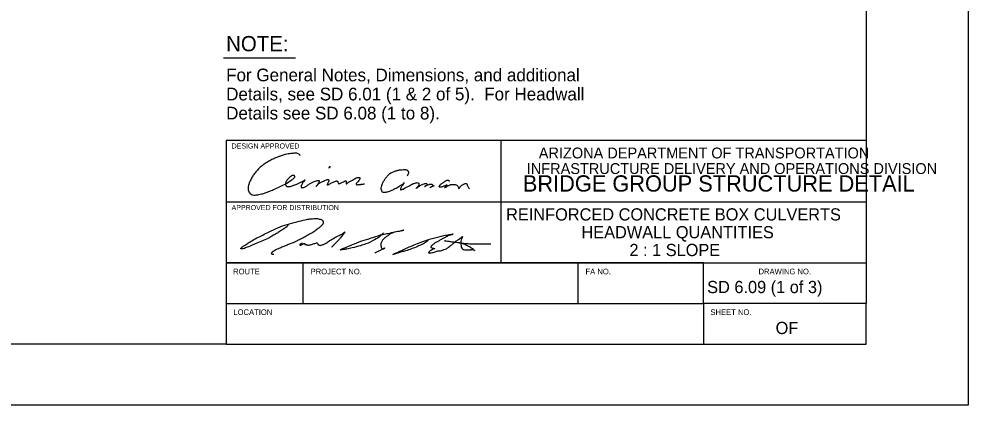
# Model space of a CAD drawing. Extents: x -0.08 to 2.83, y -0.03 to 1.92.
# Drawn here: x 1.862 to 2.833, y 0 to 0.395 of the extents above; entities that cross this region are included whole.
import ezdxf

# ---------------------------------------------------------------- set-up
doc = ezdxf.new("R2010")
doc.units = 0
for name, color, linetype in [('55', 7, 'Continuous'), ('57', 7, 'Continuous'), ('62', 7, 'Continuous'), ('63', 7, 'Continuous')]:
    doc.layers.add(name, color=color, linetype=linetype)

msp = doc.modelspace()

# ---------------------------------------------------------------- linework, layer by layer
at = {"layer": '55'}
for points in [[(2.15001, 0.25543), (2.14758, 0.25741), (2.14617, 0.25785), (2.14423, 0.25794), (2.14225, 0.25776), (2.1402, 0.25761), (2.13722, 0.2572), (2.13461, 0.25674), (2.13312, 0.25633), (2.13139, 0.2557), (2.1309, 0.25548), (2.1279, 0.25446), (2.12484, 0.2532), (2.1206, 0.25132), (2.11648, 0.24906), (2.11297, 0.24683), (2.10987, 0.24445), (2.10588, 0.24062), (2.10299, 0.237), (2.10059, 0.23378), (2.09857, 0.22978), (2.09735, 0.22698), (2.09658, 0.22347), (2.09632, 0.22083), (2.0965, 0.22021), (2.09681, 0.21951), (2.09723, 0.21833), (2.098, 0.21721), (2.09936, 0.21582), (2.101, 0.2152), (2.10355, 0.21505), (2.10736, 0.21566), (2.10994, 0.21625), (2.11399, 0.21726), (2.11746, 0.21865), (2.1224, 0.22067), (2.12858, 0.22356), (2.13414, 0.22632), (2.14122, 0.23075), (2.14355, 0.23265), (2.1438, 0.23291), (2.14403, 0.23351), (2.14403, 0.23426), (2.14395, 0.23467), (2.14366, 0.23506), (2.14306, 0.23523), (2.14231, 0.23519), (2.14138, 0.23496), (2.14015, 0.23417), (2.13831, 0.23262), (2.1366, 0.23096), (2.1355, 0.22937), (2.13485, 0.2278), (2.13469, 0.22641), (2.13471, 0.22546), (2.13499, 0.22483), (2.13551, 0.2243), (2.13614, 0.22393), (2.13712, 0.22378), (2.13865, 0.22378), (2.14061, 0.22424), (2.1439, 0.22538), (2.14709, 0.22656), (2.14964, 0.22791), (2.15235, 0.22918), (2.1548, 0.23064), (2.15321, 0.22863), (2.15278, 0.22814), (2.15212, 0.22718), (2.15124, 0.22569), (2.15055, 0.22402), (2.15062, 0.22327), (2.15113, 0.2227), (2.15171, 0.22264), (2.15353, 0.2229), (2.15492, 0.22351), (2.15731, 0.22511), (2.15997, 0.22683), (2.16276, 0.22826), (2.16513, 0.22931), (2.1672, 0.22997), (2.16877, 0.23003), (2.16885, 0.23001), (2.16905, 0.22994), (2.16916, 0.22971), (2.16921, 0.22923), (2.16902, 0.22873), (2.16846, 0.22743), (2.1677, 0.22608), (2.16569, 0.22382), (2.16628, 0.22431), (2.16828, 0.22641), (2.16883, 0.2268), (2.16988, 0.2275), (2.1711, 0.22812), (2.17281, 0.229), (2.17455, 0.2298), (2.17652, 0.23053), (2.17805, 0.23107), (2.17845, 0.23099), (2.17884, 0.23056), (2.17886, 0.22947), (2.17831, 0.22798), (2.17796, 0.22723), (2.17731, 0.22578), (2.17716, 0.22546), (2.17716, 0.22538), (2.17753, 0.22539), (2.17821, 0.22565), (2.17895, 0.22596), (2.18003, 0.22647), (2.18113, 0.22707), (2.18425, 0.22854), (2.18595, 0.22925), (2.18701, 0.22947), (2.18751, 0.22945), (2.18764, 0.22938), (2.18777, 0.22927), (2.18805, 0.22878), (2.18849, 0.22777), (2.18919, 0.22648), (2.1903, 0.2268), (2.19162, 0.22742), (2.19305, 0.22818), (2.19472, 0.22898), (2.1958, 0.22955), (2.19618, 0.2297), (2.19652, 0.22948), (2.19677, 0.22899), (2.19681, 0.22851), (2.19688, 0.22708), (2.19689, 0.22654), (2.19699, 0.2265), (2.19794, 0.22713), (2.20054, 0.22882), (2.20306, 0.23041), (2.20516, 0.23164), (2.20697, 0.23255), (2.20839, 0.23299), (2.21006, 0.23312), (2.2106, 0.23289), (2.21082, 0.23247), (2.2109, 0.23199), (2.21081, 0.23152), (2.2104, 0.23086), (2.20965, 0.2299), (2.20831, 0.22816), (2.20712, 0.22678), (2.20699, 0.22618), (2.20715, 0.22586), (2.2085, 0.22567), (2.20942, 0.22576), (2.21055, 0.22588), (2.21161, 0.22603), (2.21247, 0.22616), (2.21418, 0.22636), (2.21539, 0.22668)], [(2.17986, 0.24471), (2.17999, 0.24419), (2.17945, 0.24328), (2.17891, 0.24254), (2.18016, 0.24389), (2.18061, 0.24401)], [(2.25913, 0.23472), (2.26029, 0.23637), (2.26076, 0.23774), (2.26076, 0.23856), (2.26062, 0.23911), (2.26004, 0.23992), (2.25945, 0.24026), (2.2583, 0.24058), (2.25644, 0.2408), (2.25422, 0.2407), (2.25114, 0.2404), (2.24777, 0.23963), (2.2448, 0.23864), (2.24155, 0.23685), (2.23882, 0.23456), (2.2377, 0.23304), (2.2365, 0.23153), (2.23482, 0.22905), (2.23317, 0.22562), (2.23251, 0.22313), (2.2323, 0.22157), (2.2325, 0.22061), (2.23275, 0.2199), (2.23334, 0.21882), (2.23414, 0.21819), (2.23498, 0.21801), (2.2361, 0.21789), (2.23696, 0.21795), (2.23781, 0.21809), (2.23899, 0.21844), (2.24106, 0.21913), (2.24338, 0.21998), (2.24568, 0.22106), (2.24791, 0.22222), (2.25148, 0.22431), (2.25408, 0.22593), (2.25528, 0.22699), (2.25596, 0.22758), (2.2558, 0.22724), (2.25569, 0.22701), (2.25442, 0.2253), (2.25333, 0.22375), (2.25269, 0.22234), (2.25245, 0.22167), (2.25221, 0.22097), (2.25221, 0.22077), (2.25227, 0.22059), (2.25263, 0.22047), (2.25298, 0.22053), (2.2536, 0.22067), (2.25502, 0.22125), (2.26074, 0.22419), (2.26545, 0.22673), (2.26732, 0.22736), (2.26877, 0.22774), (2.26999, 0.22768), (2.27076, 0.22738), (2.27111, 0.22675), (2.27112, 0.22556), (2.27102, 0.22481), (2.27061, 0.22411), (2.26819, 0.22181), (2.27093, 0.22373), (2.27398, 0.22556), (2.27644, 0.22654), (2.27843, 0.22689), (2.27927, 0.22661), (2.27985, 0.2258), (2.27977, 0.22554), (2.27976, 0.22537), (2.27941, 0.22518), (2.2786, 0.22453), (2.27706, 0.22375), (2.27972, 0.22513), (2.28179, 0.22589), (2.28256, 0.22619), (2.28403, 0.22629), (2.28469, 0.22599), (2.28517, 0.22525), (2.28515, 0.22471), (2.28492, 0.22428), (2.28393, 0.22344), (2.28235, 0.22249), (2.28532, 0.22412), (2.28733, 0.22492)], [(2.30267, 0.22892), (2.30234, 0.22949), (2.3018, 0.22993), (2.30131, 0.23009), (2.3008, 0.23009), (2.30032, 0.23003), (2.29957, 0.22989), (2.29894, 0.22961), (2.29775, 0.22894), (2.29677, 0.22833), (2.29582, 0.22761), (2.29429, 0.22651), (2.29321, 0.22567), (2.29216, 0.2246), (2.29189, 0.22405), (2.2918, 0.22362), (2.29182, 0.22366), (2.29199, 0.22348), (2.29251, 0.22335), (2.2936, 0.22339), (2.29501, 0.22377), (2.29629, 0.22413), (2.29798, 0.2247), (2.29932, 0.22536), (2.29957, 0.22541), (2.29976, 0.2253), (2.29981, 0.2252), (2.29975, 0.225), (2.29959, 0.2248), (2.29831, 0.22373), (2.29744, 0.22287), (2.29735, 0.22276), (2.29743, 0.2227), (2.29781, 0.22277), (2.2988, 0.22329), (2.30057, 0.22435), (2.30188, 0.225), (2.30392, 0.22573), (2.3061, 0.22604), (2.30849, 0.22581), (2.30949, 0.22544), (2.31036, 0.22475), (2.31091, 0.22411), (2.3116, 0.22265), (2.31196, 0.22161), (2.3126, 0.22233), (2.31334, 0.22346), (2.31434, 0.22457), (2.31582, 0.22566), (2.31756, 0.2264), (2.31949, 0.22699), (2.31976, 0.22691), (2.32023, 0.22668), (2.3207, 0.22516), (2.32126, 0.22398), (2.32189, 0.22286), (2.32233, 0.22209), (2.32292, 0.22145)], [(2.13692, 0.18516), (2.13711, 0.18449), (2.13708, 0.18402), (2.13681, 0.18349), (2.13589, 0.18255), (2.13195, 0.17982), (2.12821, 0.17738), (2.12437, 0.17504), (2.11671, 0.17069), (2.10374, 0.16502), (2.10229, 0.16443), (2.09999, 0.1634), (2.09376, 0.16092), (2.09139, 0.16014), (2.09018, 0.15994), (2.08919, 0.15985), (2.08904, 0.15989), (2.08875, 0.16017), (2.08886, 0.16035), (2.08914, 0.16074), (2.09001, 0.16165), (2.09361, 0.16401), (2.0971, 0.16634), (2.1021, 0.16941), (2.10864, 0.17274), (2.11998, 0.17836), (2.1292, 0.18259), (2.13862, 0.18561), (2.14876, 0.18833), (2.15642, 0.19001), (2.16054, 0.19071), (2.1641, 0.1909), (2.16637, 0.19094), (2.1683, 0.19075), (2.17023, 0.19028), (2.1718, 0.18974), (2.17245, 0.18918), (2.17281, 0.18877), (2.17307, 0.18808), (2.17324, 0.18741), (2.17323, 0.18698), (2.17317, 0.1864), (2.17305, 0.18598), (2.17272, 0.18537), (2.17195, 0.18431), (2.17071, 0.18308), (2.16807, 0.18073), (2.16459, 0.17812), (2.16054, 0.17558), (2.15565, 0.17281), (2.15245, 0.171), (2.14775, 0.16877), (2.14512, 0.16756), (2.13957, 0.16509), (2.1355, 0.16347), (2.13193, 0.16192), (2.12769, 0.16032), (2.12482, 0.15889), (2.12278, 0.15776), (2.12183, 0.1571), (2.12131, 0.15676), (2.12086, 0.15632), (2.12046, 0.15586), (2.12012, 0.15542), (2.12011, 0.15537), (2.12011, 0.15526), (2.1202, 0.15509), (2.12036, 0.15488), (2.12062, 0.15472), (2.12115, 0.15459), (2.12156, 0.15459), (2.12236, 0.15462), (2.12266, 0.15463)], [(2.15215, 0.16533), (2.15165, 0.16558), (2.15087, 0.16542), (2.1497, 0.16466), (2.14918, 0.16411), (2.14918, 0.16383), (2.1495, 0.16362), (2.15043, 0.16388), (2.15113, 0.16407), (2.15248, 0.16463), (2.15357, 0.16535), (2.15403, 0.16543), (2.15418, 0.16544), (2.15443, 0.16515), (2.1544, 0.16455), (2.15476, 0.16431), (2.15544, 0.16432), (2.15619, 0.16415), (2.15697, 0.16398), (2.15772, 0.16378), (2.15893, 0.16383), (2.1601, 0.16421), (2.16212, 0.16481), (2.16403, 0.16537), (2.16566, 0.16582), (2.16712, 0.16606), (2.16767, 0.16496), (2.16804, 0.16429), (2.1689, 0.16384), (2.17004, 0.16347), (2.17128, 0.16384), (2.17298, 0.16426), (2.1762, 0.16591), (2.18, 0.16838), (2.18508, 0.17145), (2.19087, 0.17445), (2.1937, 0.17599), (2.19558, 0.1773), (2.19408, 0.17539), (2.19361, 0.17483), (2.193, 0.17404), (2.19158, 0.17212), (2.19036, 0.17057), (2.18805, 0.16806), (2.18628, 0.16609), (2.18362, 0.16346), (2.18164, 0.16142)], [(2.23491, 0.17651), (2.23186, 0.17315), (2.22584, 0.16918), (2.21679, 0.16499), (2.21159, 0.16321), (2.20276, 0.1609), (2.19747, 0.15972), (2.19293, 0.15912), (2.19072, 0.15909), (2.19235, 0.15989), (2.19737, 0.16193), (2.20515, 0.16517), (2.21517, 0.16888), (2.22498, 0.17188), (2.23419, 0.17479), (2.23965, 0.17583), (2.24639, 0.17729), (2.25314, 0.1786), (2.25576, 0.17906), (2.25005, 0.17775), (2.24376, 0.17607), (2.24298, 0.17572), (2.24203, 0.1753), (2.24067, 0.17435), (2.23819, 0.17259), (2.23585, 0.17076), (2.2335, 0.16821), (2.23281, 0.1669), (2.23236, 0.16519), (2.23225, 0.16307), (2.23247, 0.16233), (2.2327, 0.16154), (2.23327, 0.16046), (2.23374, 0.16008), (2.23426, 0.15985), (2.23515, 0.16001), (2.23578, 0.16029), (2.2364, 0.16088), (2.23548, 0.16053), (2.23352, 0.15952), (2.23198, 0.15863), (2.23092, 0.15801), (2.22859, 0.15697), (2.227, 0.15624), (2.22607, 0.15571)], [(2.28075, 0.16875), (2.27797, 0.16654), (2.27366, 0.16413), (2.26825, 0.16177), (2.26206, 0.15933), (2.25657, 0.15761), (2.25242, 0.15648), (2.24459, 0.1543), (2.24926, 0.15636), (2.25262, 0.1578), (2.25725, 0.16014), (2.26258, 0.16247), (2.26991, 0.16539), (2.27822, 0.16854), (2.28481, 0.17056), (2.29031, 0.17203), (2.29538, 0.17324), (2.30109, 0.17436), (2.30588, 0.17543), (2.30606, 0.17546), (2.30606, 0.17525), (2.30316, 0.17414), (2.3009, 0.17315), (2.29924, 0.17223), (2.29807, 0.17157), (2.29507, 0.17014), (2.29189, 0.16831), (2.28907, 0.16674), (2.28671, 0.16521), (2.28453, 0.16333), (2.28365, 0.16246), (2.28334, 0.16199), (2.28345, 0.1616), (2.28392, 0.16118), (2.28531, 0.16081), (2.28728, 0.16045), (2.28749, 0.16038), (2.28753, 0.16024), (2.28657, 0.15987), (2.2841, 0.15862), (2.28248, 0.15764), (2.2816, 0.15684), (2.28122, 0.15623), (2.28119, 0.15602), (2.28133, 0.15581), (2.28226, 0.15582), (2.28517, 0.15615), (2.28673, 0.1566), (2.28889, 0.15734), (2.29045, 0.15779), (2.29226, 0.15803), (2.29432, 0.15824), (2.29669, 0.15913), (2.29931, 0.16013), (2.30238, 0.16221), (2.30477, 0.16406), (2.30941, 0.16804), (2.31103, 0.1692), (2.31434, 0.17146), (2.31581, 0.17269), (2.31451, 0.16933), (2.31413, 0.1664), (2.31439, 0.16328), (2.31521, 0.16058), (2.31694, 0.1594), (2.32065, 0.15881), (2.32285, 0.15892), (2.32308, 0.15901), (2.32329, 0.15919), (2.32353, 0.15911), (2.32364, 0.159), (2.32467, 0.15907), (2.32563, 0.1593), (2.32699, 0.15903), (2.32804, 0.15819), (2.32817, 0.1581), (2.32825, 0.15812), (2.32825, 0.1582), (2.32813, 0.15837), (2.32721, 0.15911), (2.32701, 0.15927), (2.32506, 0.16076), (2.32392, 0.16151), (2.32032, 0.16332), (2.31627, 0.16522), (2.315, 0.16561), (2.31286, 0.166), (2.30979, 0.16645), (2.30602, 0.16682), (2.30209, 0.16741), (2.29903, 0.16786), (2.29731, 0.16826), (2.30287, 0.16758), (2.31104, 0.16647), (2.31894, 0.16545), (2.32442, 0.16523), (2.33099, 0.16521), (2.3432, 0.1651), (2.34473, 0.16507)]]:
    msp.add_spline(points, degree=3, dxfattribs=at)
at = {"layer": '57'}
msp.add_line((2.07131, 0.3556), (2.14477, 0.3556), dxfattribs=at)
at = {"layer": '63'}
for p, q in [((2.83333, 1.83333), (2.83333, 0)), ((2.72918, 0.27077), (2.07387, 0.27077)), ((2.07387, 0.27077), (2.07387, 0.06244)), ((2.35493, 0.27077), (2.35493, 0.14578)), ((2.57284, 0.27077), (2.57284, 0.27077)), ((2.07387, 0.20828), (2.72918, 0.20828)), ((2.07387, 0.14578), (2.72918, 0.14578)), ((2.08908, 0.14583), (2.08931, 0.14583)), ((2.15266, 0.10411), (2.15266, 0.14578)), ((2.23742, 0.14583), (2.23742, 0.14583)), ((2.23742, 0.14583), (2.23742, 0.14583)), ((2.23742, 0.14583), (2.23742, 0.14583)), ((2.23742, 0.14583), (2.23742, 0.14583)), ((2.43435, 0.10411), (2.43435, 0.14578)), ((2.07387, 0.10411), (2.56251, 0.10411)), ((2.56251, 0.10411), (2.56251, 0.06244)), ((2.72918, 0.06244), (2.72918, 0.10411)), ((2.07387, 0.06244), (2.72918, 0.06244)), ((2.83333, 0), (0, 0)), ((2.83, 0.00033), (2.83, 0.00033))]:
    msp.add_line(p, q, dxfattribs=at)
msp.add_lwpolyline([(0.16668, 0.06244), (0.16668, 1.77077), (2.72918, 1.77077), (2.72918, 0.10411), (2.56251, 0.10411), (2.56251, 0.14578), (2.07387, 0.14578), (2.07387, 0.06244)], close=True, dxfattribs=at)

# ---------------------------------------------------------------- texts
at = {"layer": '55'}
for s, p in [('DESIGN APPROVED', (2.07944, 0.26274)), ('APPROVED FOR DISTRIBUTION', (2.07944, 0.19966))]:
    msp.add_text(s, height=0.0052084, dxfattribs=at).set_placement(p)
at = {"layer": '57'}
for s, height, p in [('NOTE:', 0.015625, (2.07387, 0.36231)), ('For General Notes, Dimensions, and additional', 0.0130208, (2.07387, 0.33154)), ('Details, see SD 6.01 (1 & 2 of 5).  For Headwall', 0.0130208, (2.07387, 0.31201)), ('Details see SD 6.08 (1 to 8).', 0.0130208, (2.07387, 0.29248))]:
    msp.add_text(s, height=height, dxfattribs=at).set_placement(p)
at = {"layer": '62'}
for s, p in [('REINFORCED CONCRETE BOX CULVERTS', (2.3605, 0.189)), ('HEADWALL QUANTITIES', (2.43762, 0.17078)), ('2 : 1 SLOPE', (2.48672, 0.15255)), ('SD 6.09 (1 of 3)', (2.56631, 0.11464))]:
    msp.add_text(s, height=0.0125, dxfattribs=at).set_placement(p)
at = {"layer": '63'}
for s, height, p in [('ARIZONA DEPARTMENT OF TRANSPORTATION', 0.0111083, (2.39394, 0.25258)), ('INFRASTRUCTURE DELIVERY AND OPERATIONS DIVISION', 0.0111083, (2.38162, 0.23663)), ('BRIDGE GROUP STRUCTURE DETAIL', 0.0166667, (2.37762, 0.2186)), ('ROUTE', 0.005833, (2.08105, 0.13383)), ('PROJECT NO.', 0.0058333, (2.16034, 0.13383)), ('FA NO.', 0.005833, (2.44175, 0.13383)), ('DRAWING NO.', 0.0058334, (2.61888, 0.13383)), ('LOCATION', 0.005833, (2.08128, 0.09217)), ('SHEET NO.', 0.005833, (2.56964, 0.09217)), ('OF', 0.0125, (2.63638, 0.0727))]:
    msp.add_text(s, height=height, dxfattribs=at).set_placement(p)

doc.saveas('drawing.dxf')
